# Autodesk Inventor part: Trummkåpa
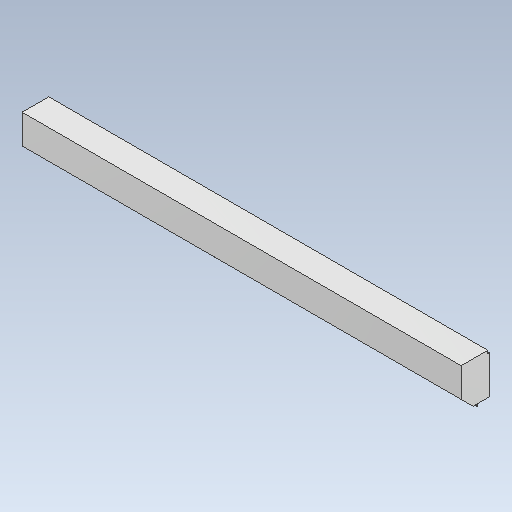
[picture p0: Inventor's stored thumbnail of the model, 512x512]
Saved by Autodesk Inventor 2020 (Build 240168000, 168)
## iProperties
Created: 2019-06
Part Number: Trummkåpa
Material: Aluminum
Document SubType Name: Modeling
Designer: cl
Density: 2.7 g/cm^3
Appearance: Satin
Author: cl
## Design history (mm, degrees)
sketch "Sketch1"
  geometry: L1 (0, 0)-(20, 0); L2 (20, 0)-(20, 32.56); L3 (20, 32.56)-(107.427, 119.987); L4 (107.427, 119.987)-(320.917, 119.987); L5 (320.917, 119.987)-(320.917, -75.013); L6 (320.917, -75.013)-(296.917, -75.013); L7 (296.917, -75.013)-(296.917, -90.013); L8 (296.917, -90.013)-(20.987, -90.013); L9 (0, 0)-(0, -2); L10 (0, -2)-(20.987, -2); L11 (20.987, -2)-(20.987, -90.013)
  constraints: 22 end point, 7 perpendicular, 1 horizontal, 1 parallel, 1 vertical
  dimensions: "d0" = 20 distance of L1.start L1.end; "d1" = 32.56 distance of L1.end L2.end; "d2" = 123.64 distance of L2.end L3.end; "d3" = 135 deg angle of L2 L3; "d4" = 213.49 distance of L3.end L4.end; "d5" = 195 distance of L4.end L5.end; "d6" = 24 distance of L5.end L6.end; "d7" = 15 distance of L6.end L7.end; "d8" = 275.93 distance of L7.end L8.end; "d10" = 2 distance of L1.start L9.end
extrude "Extrusion1" new body sketch "Sketch1" distance "d11" = 3210 (computed from Dagbredd); taper "d12" = 0 deg
body "Solid1"
